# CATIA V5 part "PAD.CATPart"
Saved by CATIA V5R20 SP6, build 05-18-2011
Part number: PAD
Bounding box of the stored display mesh (mm): x -136.104 to -79.973, y -770.564 to -752.248, z 47.549 to 209.63
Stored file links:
  C:\V5_education\Assemble Design\CATProduct\Disk brake\PAD.CATPart
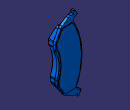
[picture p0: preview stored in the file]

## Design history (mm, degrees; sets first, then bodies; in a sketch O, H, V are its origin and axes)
Body1 "PartBody ( *SOL27 - wsp *MASTER -  )" (main body)
  Solid1 "Solid.1 (  with JELE 2117 : from *SOL27 - wsp *MASTER -  ) ( Brep from *SOL27 )": solid without history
